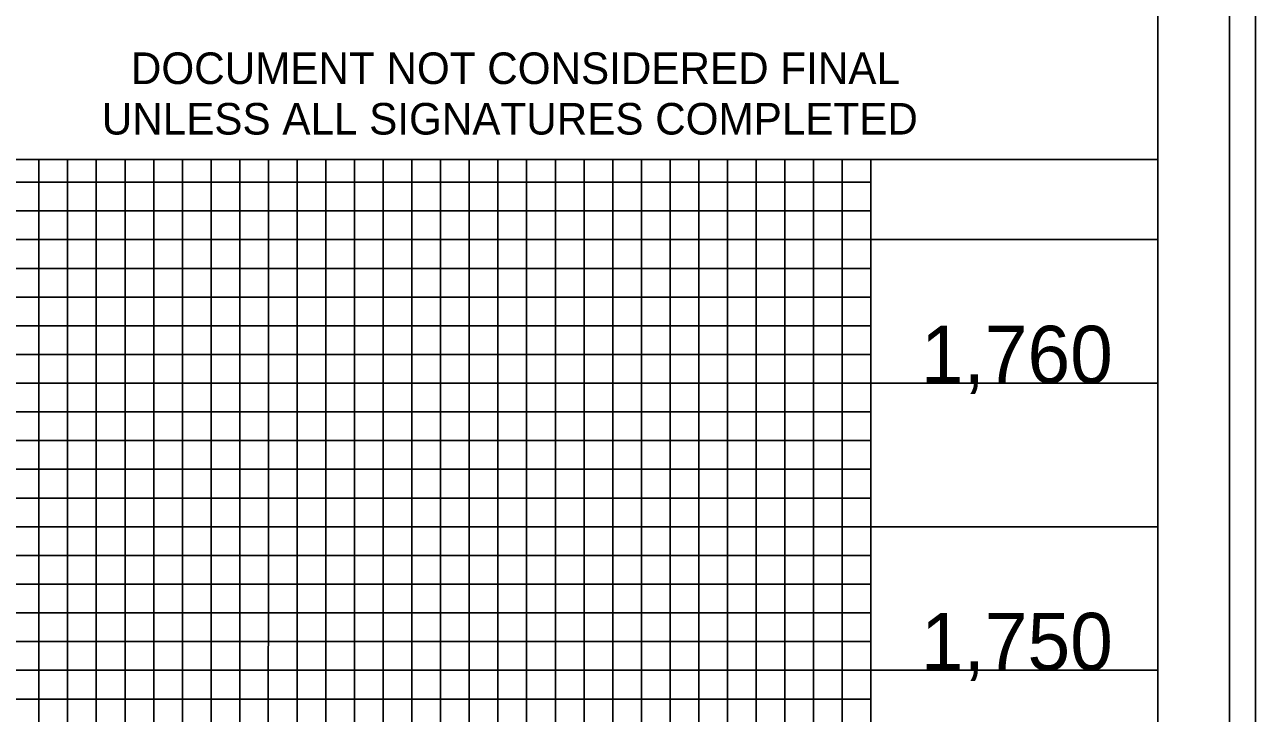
# Model space of a CAD drawing. Extents: x 505237 to 506921, y 424821 to 425921.
# Drawn here: x 506706.2 to 506920.7, y 425638.2 to 425758.1 of the extents above; entities that cross this region are included whole.
import ezdxf

# ---------------------------------------------------------------- set-up
doc = ezdxf.new("R2010")
doc.units = 0
for name, color, linetype in [('Exist Vertical Profile Vertical Axis Label', 7, 'Continuous'), ('Matchline', 7, 'Continuous'), ('Prop Horizontal Alignment Station Label', 7, 'Continuous'), ('Sheet Cutting Line CELL', 7, 'Continuous'), ('Sheet DOT Grid CELL', 7, 'Continuous'), ('Sheet Plot Border Inside CELL', 7, 'Continuous'), ('Sheet Plot Border Outside CELL', 7, 'Continuous'), ('Sheet Sticker Exception Certification CELL', 7, 'Continuous'), ('Sheet Sticker Incomplete CELL', 7, 'Continuous')]:
    doc.layers.add(name, color=color, linetype=linetype)

msp = doc.modelspace()

# ---------------------------------------------------------------- linework, layer by layer
at = {"layer": 'Matchline'}
for points in [[(506378.71, 425395.67), (506428.71, 425395.67), (506428.71, 425895.67), (506478.71, 425895.67), (506478.71, 425395.67), (506528.71, 425395.67), (506528.71, 425895.67), (506578.71, 425895.67), (506578.71, 425395.67), (506628.71, 425395.67), (506628.71, 425895.67), (506678.71, 425895.67), (506678.71, 425395.67), (506728.71, 425395.67), (506728.71, 425734.62)], [(506728.71, 425658.47), (506728.71, 425395.67), (506778.71, 425395.67), (506778.71, 425734.62)], [(506778.71, 425658.47), (506778.71, 425395.67), (506828.71, 425395.67), (506828.71, 425734.62)], [(506903.71, 425720.67), (505403.71, 425720.67), (505403.71, 425670.67), (506728.71, 425670.67)], [(506728.71, 425670.67), (506903.71, 425670.67)]]:
    msp.add_lwpolyline(points, dxfattribs=at)
at = {"layer": 'Prop Horizontal Alignment Station Label'}
msp.add_lwpolyline([(506903.71, 425895.67), (505403.71, 425895.67), (505403.71, 424845.67), (506903.71, 424845.67)], close=True, dxfattribs=at)
at = {"layer": 'Sheet Cutting Line CELL'}
for points in [[(506853.71, 425734.62), (506853.71, 425395.67), (506903.71, 425395.67), (506903.71, 425745.67)], [(506753.71, 425734.62), (506753.71, 425395.67), (506803.71, 425395.67), (506803.71, 425395.67), (506803.71, 425734.62)], [(506903.71, 425695.67), (505403.71, 425695.67), (505403.71, 425645.67), (506903.71, 425645.67)]]:
    msp.add_lwpolyline(points, dxfattribs=at)
at = {"layer": 'Sheet DOT Grid CELL'}
for p, q in [((506753.71, 425395.67), (506753.71, 425734.62)), ((506803.71, 425395.67), (506803.71, 425734.62)), ((506853.71, 425395.67), (506853.71, 425734.62)), ((506903.71, 425695.67), (505403.71, 425695.67)), ((506903.71, 425645.67), (505403.71, 425645.67))]:
    msp.add_line(p, q, dxfattribs=at)
at = {"layer": 'Sheet Plot Border Inside CELL'}
msp.add_lwpolyline([(505249.71, 424843.12), (506916.21, 424843.12), (506916.21, 425898.22), (505249.71, 425898.22)], close=True, dxfattribs=at)
at = {"layer": 'Sheet Plot Border Outside CELL'}
msp.add_lwpolyline([(505236.71, 424820.67), (506920.71, 424820.67), (506920.71, 425920.67), (505236.71, 425920.67)], close=True, dxfattribs=at)
at = {"layer": 'Sheet Sticker Exception Certification CELL'}
for p, q in [((506903.7, 425758.11), (506903.7, 425734.61)), ((506903.7, 425758.11), (506903.7, 425734.61)), ((506903.7, 425734.62), (506703.66, 425734.62)), ((506903.7, 425734.62), (506703.66, 425734.62))]:
    msp.add_line(p, q, dxfattribs=at)
at = {"layer": 'Sheet Sticker Incomplete CELL'}
for p, q in [((505453.71, 425730.67), (506853.71, 425730.67)), ((506853.71, 425710.67), (505453.71, 425710.67)), ((505453.71, 425705.67), (506853.71, 425705.67)), ((506853.71, 425685.67), (505453.71, 425685.67)), ((505453.71, 425680.67), (506853.71, 425680.67)), ((506853.71, 425660.67), (505453.71, 425660.67)), ((505453.71, 425655.67), (506853.71, 425655.67)), ((506853.71, 425650.67), (505453.71, 425650.67)), ((505453.71, 425640.67), (506853.71, 425640.67))]:
    msp.add_line(p, q, dxfattribs=at)
for points in [[(506708.71, 425734.62), (506708.71, 425395.67), (506713.71, 425395.67), (506713.71, 425734.62)], [(506718.71, 425734.62), (506718.71, 425395.67), (506723.71, 425395.67), (506723.71, 425734.62)], [(506733.71, 425734.62), (506733.71, 425395.67), (506733.71, 425395.67), (506738.71, 425395.67), (506743.71, 425395.67), (506743.71, 425734.62)], [(506738.71, 425734.62), (506738.71, 425395.67)], [(506748.71, 425734.62), (506748.61, 425395.72), (506753.61, 425395.72), (506758.71, 425395.67), (506758.71, 425734.62)], [(506758.71, 425658.47), (506758.71, 425395.67), (506763.71, 425395.67), (506763.71, 425734.62)], [(506768.71, 425734.62), (506768.71, 425395.67), (506773.71, 425395.67), (506773.71, 425734.62)], [(506783.71, 425734.62), (506783.71, 425395.67), (506788.71, 425395.67), (506788.71, 425734.62)], [(506793.71, 425734.62), (506793.71, 425395.67), (506798.71, 425395.67), (506798.71, 425734.62)], [(506808.71, 425734.62), (506808.71, 425395.67), (506813.71, 425395.67), (506813.71, 425734.62)], [(506818.71, 425734.62), (506818.71, 425395.67), (506823.71, 425395.67), (506823.71, 425734.62)], [(506833.71, 425734.62), (506833.71, 425395.67), (506838.71, 425395.67), (506838.71, 425734.62)], [(506843.71, 425734.62), (506843.71, 425395.67), (506848.71, 425395.67), (506848.71, 425734.62)], [(506853.71, 425725.67), (505453.71, 425725.67), (505453.71, 425715.67), (506853.71, 425715.67)], [(506853.71, 425700.67), (505453.71, 425700.67), (505453.71, 425690.67), (506853.71, 425690.67)], [(506853.71, 425675.67), (505453.71, 425675.67), (505453.71, 425665.67), (506853.71, 425665.67)]]:
    msp.add_lwpolyline(points, dxfattribs=at)

# ---------------------------------------------------------------- texts
at = {"layer": 'Exist Vertical Profile Vertical Axis Label'}
for s, p in [('1,760', (506862.41, 425695.67)), ('1,750', (506862.41, 425645.67))]:
    msp.add_text(s, height=10, dxfattribs=at).set_placement(p)
at = {"layer": 'Sheet Sticker Exception Certification CELL'}
for s, p in [('DOCUMENT NOT CONSIDERED FINAL', (506724.74, 425747.77)), ('DOCUMENT NOT CONSIDERED FINAL', (506724.74, 425747.77)), ('UNLESS ALL SIGNATURES COMPLETED', (506719.66, 425738.97)), ('UNLESS ALL SIGNATURES COMPLETED', (506719.66, 425738.97))]:
    msp.add_text(s, height=5.5, dxfattribs=at).set_placement(p)

doc.saveas('drawing.dxf')
